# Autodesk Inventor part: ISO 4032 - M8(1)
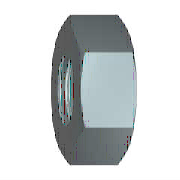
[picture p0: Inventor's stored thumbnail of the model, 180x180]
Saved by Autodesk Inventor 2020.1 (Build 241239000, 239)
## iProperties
Created: 2019-01
Part Number: ISO 4032 - M8(1)
Material: Edelstahl, 440C
Description: Sechskantmutter
Document SubType Name: Modeling
Standard: ISO 4032
Designer: lutzd
Standards Organization: DIN
Language: de-DE
Size Designation: M8
Categories: <MemberInstance><Categories><Category DisplayName="Verbindungselemente" InternalName="e4da775c-781d-43d5-af7c-5136215cf5a6" Mnemonic="FSTN"><Category DisplayNam
Mass: 5.63002 g
Surface Area: 6.18292 cm^2
Volume: 0.726454 cm^3
Density: 7.75 g/cm^3
Appearance: Halbpoliert
IsCustomPart: 0
Author: lutzd
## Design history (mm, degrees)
workaxis "Work Axis1"
workplane "Work Plane1"
sketch "Skizze1"
  geometry: L1 (-7.506, 0)-(-3.753, 6.5); L2 (-3.753, 6.5)-(3.753, 6.5); L3 (3.753, 6.5)-(7.506, 0); L4 (7.506, 0)-(3.753, -6.5); L5 (3.753, -6.5)-(-3.753, -6.5); L6 (-3.753, -6.5)-(-7.506, 0); 2 further points
  constraints: 12 end point, 1 coincident, 1 horizontal, 11 other
  dimensions: "d0" = 15.01111 distance of L3.end L1.start (= 1.1547 x SW)
extrude "Körper" new body sketch "Skizze1" distance "d1" = 6.8 (= KOH); taper "d2" = 0 deg
sketch "Skizze2"
  geometry: L1 (0, 3.753)-(0, 7.506) reference; L2 (0, 7.506)-(6.8, 7.506) reference; L3 (6.8, 3.753)-(6.8, 7.506) reference; L4 (-1.36, 0)-(8.16, 0) reference; L5 (0.985, 7.506)-(0, 5.8); L6 (5.815, 7.506)-(6.8, 5.8)
  constraints: 4 end point, 4 point on line
  dimensions: "d3" = 30 deg angle of L1 L5 (= ANG1); "d4" = 30 deg angle of L3 L6 (= ANG2); "d5" = 11.6 diameter of L5.end L4 (= SW0); "d6" = 11.6 diameter of L6.end L4 (= SW01)
revolve "Fase1" stored, may be unused: angle "d7" = 90 deg
sketch "Skizze3"
  geometry: 4 further points
  constraints: 1 coincident, 1 other
hole "Gewinde" sketch "Skizze3" diameter "d25" = 6.647; stored, may be unused: countersink angle "d29" = 82 deg, drill point angle "d31" = 118 deg; dims "d26" = 6, "d27" = 4, "d28" = 2, "d30" = 8
body "Solid1"
chamfer "Fase2" distance "d8" = 0.67658 (= -0.5 x GD1 + 0.5 x NND); stored, may be unused: angle "d9" = 30 deg, second distance "d40" = 0.67658 (= -0.5 x GD1 + 0.5 x NND)
chamfer "Fase3" distance "d10" = 0.67658 (= -0.5 x GD1 + 0.5 x NND); stored, may be unused: angle "d11" = 30 deg, second distance "d41" = 0.67658 (= -0.5 x GD1 + 0.5 x NND)
other parameters: "ANG1" = 30 deg [user parameter; used in 1 equation term], "ANG2" = 30 deg [user parameter; used in 1 equation term], "NND" = 8 [user parameter; used in 4 equation terms], "KOH" = 6.8 [user parameter; used in 1 equation term], "SW" = 13 [user parameter; used in 2 equation terms], "SW0" = 11.6 [user parameter; used in 1 equation term], "SW01" = 11.6 [user parameter; used in 1 equation term], "GD1" = 6.64684 (computed from THREADDIA, PTC, TOA) [user parameter; used in 4 equation terms], "d13" = 0, "d14" = 0, "d39" = 0, "d42" = 0, "GUL" = 0.67658 (= 0.541266 x PTC) [user parameter], "TPU" = 8 (computed from PTC) [user parameter], "THREADDIA" = 8 [user parameter; used in 1 equation term], "TOA" = 30 deg [user parameter; used in 1 equation term], "PTC" = 1.25 [user parameter; used in 4 equation terms], "E0" = 15.015 (= 1.155 x SW) [user parameter], "GAL" = 0.67658 (= 0.541266 x PTC) [user parameter]
